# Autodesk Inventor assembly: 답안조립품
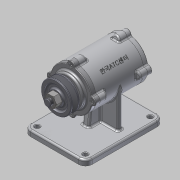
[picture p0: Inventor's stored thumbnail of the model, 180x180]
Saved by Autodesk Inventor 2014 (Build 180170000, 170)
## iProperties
Created: 2015-12
Part Number: 답안조립품
Document SubType Name: Assembly
Designer: L10
Author: L10
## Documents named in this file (11)
- C:\Users\L10\Desktop\451208V1012\답안조립품.iam
- C:\Users\L10\Desktop\451208V1012\본체.ipt
- C:\Users\L10\Desktop\451208V1012\V-벨트풀리.ipt
- C:\Users\L10\Desktop\451208V1012\너트 M12x1.25.ipt
- C:\Users\L10\Desktop\451208V1012\베어링 6204.ipt
- C:\Users\L10\Desktop\451208V1012\볼트 M4 x 12.ipt
- C:\Users\L10\Desktop\451208V1012\오일실.ipt
- C:\Users\L10\Desktop\451208V1012\축.ipt
- C:\Users\L10\Desktop\451208V1012\커버.ipt
- C:\Users\L10\Desktop\451208V1012\커버2.ipt
- C:\Users\L10\Desktop\451208V1012\키(4 x 4 x 12).ipt
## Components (6 placed, 5 different names)
1. V-벨트풀리:1
2. KS B 1012 클래스 1 일반 - 미터 M12x1.25:1
3. KS B 2023 6204 - 20 x 47 x 14:1
4. KS B 2804 D D - 20 32 8:1
5. KS B 1311 (I) 4 x 4 x 12:1
6. KS B 2023 6204 - 20 x 47 x 14:2
